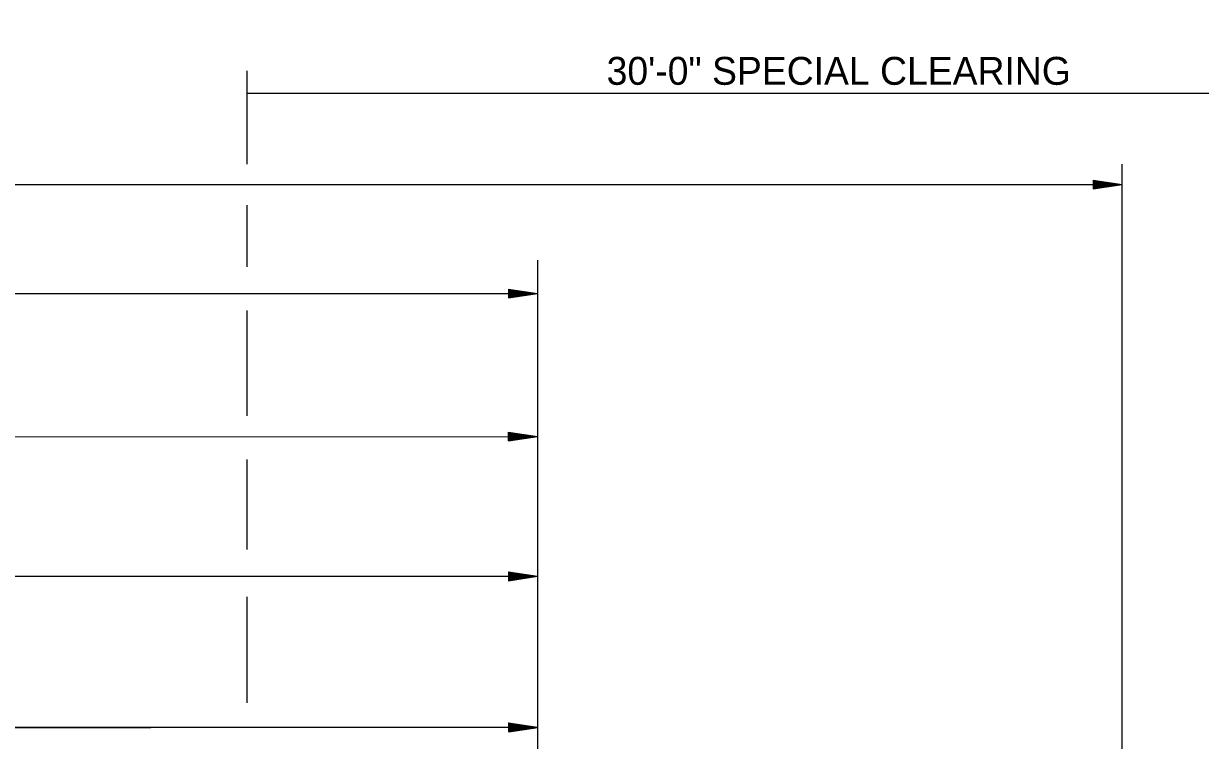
# Model space of a CAD drawing. Extents: x 1364961 to 1365294, y 367927 to 368034.
# Drawn here: x 1365224.86 to 1365249.15, y 367977.03 to 367991.83 of the extents above; entities that cross this region are included whole.
import ezdxf

# ---------------------------------------------------------------- set-up
doc = ezdxf.new("R2010")
doc.units = 0
doc.layers.add('Default', color=7, linetype='Continuous')

msp = doc.modelspace()

# ---------------------------------------------------------------- linework, layer by layer
at = {"layer": 'Default'}
for p, q in [((1365229.476, 367988.923), (1365229.476, 367990.85)), ((1365247.538, 367971.581), (1365247.538, 367988.923)), ((1365246.938, 367988.595), (1365247.538, 367988.505)), ((1365246.938, 367988.595), (1365246.938, 367988.415)), ((1365246.938, 367988.58), (1365247.438, 367988.505)), ((1365246.938, 367988.565), (1365247.335, 367988.505)), ((1365246.938, 367988.55), (1365247.235, 367988.505)), ((1365175.498, 367988.505), (1365247.538, 367988.505)), ((1365246.938, 367988.534), (1365247.133, 367988.505)), ((1365246.938, 367988.519), (1365247.033, 367988.505)), ((1365246.938, 367988.415), (1365247.538, 367988.505)), ((1365246.938, 367988.476), (1365247.133, 367988.505)), ((1365246.938, 367988.445), (1365247.335, 367988.505)), ((1365246.938, 367988.43), (1365247.438, 367988.505)), ((1365246.938, 367988.46), (1365247.235, 367988.505)), ((1365246.938, 367988.491), (1365247.033, 367988.505)), ((1365229.476, 367986.807), (1365229.476, 367988.081)), ((1365235.476, 367972.388), (1365235.476, 367986.944)), ((1365189.509, 367986.255), (1365235.476, 367986.255)), ((1365234.87, 367986.345), (1365235.47, 367986.255)), ((1365234.87, 367986.345), (1365234.87, 367986.165)), ((1365234.87, 367986.33), (1365235.37, 367986.255)), ((1365234.87, 367986.315), (1365235.267, 367986.255)), ((1365234.87, 367986.3), (1365235.167, 367986.255)), ((1365234.87, 367986.284), (1365235.065, 367986.255)), ((1365234.87, 367986.269), (1365234.965, 367986.255)), ((1365234.87, 367986.165), (1365235.47, 367986.255)), ((1365234.87, 367986.226), (1365235.065, 367986.255)), ((1365234.87, 367986.195), (1365235.267, 367986.255)), ((1365234.87, 367986.18), (1365235.37, 367986.255)), ((1365234.87, 367986.21), (1365235.167, 367986.255)), ((1365234.87, 367986.241), (1365234.965, 367986.255)), ((1365229.476, 367983.727), (1365229.476, 367985.903)), ((1365189.509, 367983.303), (1365235.476, 367983.3)), ((1365234.87, 367983.214), (1365234.871, 367983.394)), ((1365234.87, 367983.379), (1365235.37, 367983.301)), ((1365234.87, 367983.364), (1365235.267, 367983.302)), ((1365234.87, 367983.349), (1365235.167, 367983.302)), ((1365234.87, 367983.333), (1365235.065, 367983.303)), ((1365234.87, 367983.318), (1365234.965, 367983.303)), ((1365234.87, 367983.275), (1365235.065, 367983.303)), ((1365234.87, 367983.29), (1365234.965, 367983.303)), ((1365234.87, 367983.244), (1365235.267, 367983.302)), ((1365234.87, 367983.259), (1365235.167, 367983.302)), ((1365234.87, 367983.214), (1365235.47, 367983.301)), ((1365234.87, 367983.229), (1365235.37, 367983.301)), ((1365234.871, 367983.394), (1365235.47, 367983.301)), ((1365229.476, 367980.97), (1365229.476, 367982.828)), ((1365189.509, 367980.418), (1365235.476, 367980.418)), ((1365234.87, 367980.508), (1365235.47, 367980.418)), ((1365234.87, 367980.508), (1365234.87, 367980.328)), ((1365234.87, 367980.493), (1365235.37, 367980.418)), ((1365234.87, 367980.478), (1365235.267, 367980.418)), ((1365234.87, 367980.463), (1365235.167, 367980.418)), ((1365234.87, 367980.447), (1365235.065, 367980.418)), ((1365234.87, 367980.432), (1365234.965, 367980.418)), ((1365234.87, 367980.328), (1365235.47, 367980.418)), ((1365234.87, 367980.389), (1365235.065, 367980.418)), ((1365234.87, 367980.358), (1365235.267, 367980.418)), ((1365234.87, 367980.343), (1365235.37, 367980.418)), ((1365234.87, 367980.373), (1365235.167, 367980.418)), ((1365234.87, 367980.404), (1365234.965, 367980.418)), ((1365229.476, 367977.806), (1365229.476, 367979.994)), ((1365234.87, 367977.397), (1365235.47, 367977.307)), ((1365234.87, 367977.397), (1365234.87, 367977.217)), ((1365234.87, 367977.382), (1365235.37, 367977.307)), ((1365234.876, 367977.391), (1365235.476, 367977.301)), ((1365234.876, 367977.391), (1365234.876, 367977.211)), ((1365234.876, 367977.376), (1365235.376, 367977.301)), ((1365218.049, 367977.301), (1365227.487, 367977.301)), ((1365218.076, 367977.307), (1365235.476, 367977.307)), ((1365234.87, 367977.367), (1365235.267, 367977.307)), ((1365234.87, 367977.352), (1365235.167, 367977.307)), ((1365234.87, 367977.336), (1365235.065, 367977.307)), ((1365234.87, 367977.321), (1365234.965, 367977.307)), ((1365234.87, 367977.217), (1365235.47, 367977.307)), ((1365234.87, 367977.278), (1365235.065, 367977.307)), ((1365234.87, 367977.247), (1365235.267, 367977.307)), ((1365234.87, 367977.232), (1365235.37, 367977.307)), ((1365234.87, 367977.262), (1365235.167, 367977.307)), ((1365234.87, 367977.293), (1365234.965, 367977.307)), ((1365234.876, 367977.361), (1365235.273, 367977.301)), ((1365234.876, 367977.346), (1365235.173, 367977.301)), ((1365234.876, 367977.33), (1365235.071, 367977.301)), ((1365234.876, 367977.315), (1365234.971, 367977.301)), ((1365234.876, 367977.211), (1365235.476, 367977.301)), ((1365234.876, 367977.272), (1365235.071, 367977.301)), ((1365234.876, 367977.241), (1365235.273, 367977.301)), ((1365234.876, 367977.226), (1365235.376, 367977.301)), ((1365234.876, 367977.256), (1365235.173, 367977.301)), ((1365234.876, 367977.287), (1365234.971, 367977.301))]:
    msp.add_line(p, q, dxfattribs=at)
msp.add_lwpolyline([(1365229.476, 367990.387), (1365255.37, 367990.387), (1365256.227, 367991.826), (1365256.655, 367988.47), (1365257.084, 367990.387), (1365265.47, 367990.387)], dxfattribs=at)

# ---------------------------------------------------------------- texts
msp.add_text('30\'-0" SPECIAL CLEARING', height=0.576, dxfattribs=at).set_placement((1365236.897, 367990.562))

doc.saveas('drawing.dxf')
